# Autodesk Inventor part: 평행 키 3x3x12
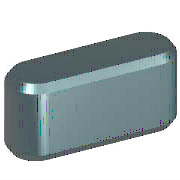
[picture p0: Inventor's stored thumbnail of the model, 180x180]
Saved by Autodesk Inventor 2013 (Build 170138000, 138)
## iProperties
IsCustomPart: 1
Created: 2012-02
Part Number: 평행 키 3x3x12
Material: 강철, 연강
Description: 평행 키
Document SubType Name: Modeling
Standard: JIS B 1301
Designer: mdu-01
Standards Organization: JIS
Language: ko-KR
Size Designation: 3x3x12
Categories: <MemberInstance><Categories><Category DisplayName="샤프트 부품" InternalName="7f7aeb1f-a693-4053-b835-cee3144e0d98" Mnemonic="SHFT"><Category DisplayName="키" Interna
Density: 1 g/cm^3
Author: mdu-01
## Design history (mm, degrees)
workplane "Work Plane1"
workplane "Work Plane2"
sketch "스케치1"
  geometry: L1 (1.5, 1.5)-(10.5, 1.5); L2 (10.5, -1.5)-(1.5, -1.5); L3 (0, 9.4)-(0, -7.4) reference; L4 (-5, 0)-(30, 0) reference; L5 (12, 0)-(12, 7); A1 r 1.5 centre (1.5, 0) between (1.5, 1.5) and (1.5, -1.5); A2 r 1.5 centre (10.5, 0) between (10.5, -1.5) and (10.5, 1.5)
  constraints: 6 end point, 5 point on circle, 4 tangent, 3 point on line, 2 centre point, 1 horizontal, 1 parallel, 1 perpendicular
  dimensions: "d0" = 1.5 radius of A1 (= 0.5 x PB); "d13" = 1.5 radius of A2 (= 0.5 x PB); "d14" = 12 distance between parallel lines of L5 L3 (= NLG)
extrude "본체1" new body sketch "스케치1" taper "d3" = 0 deg; stored distance "d4" = 10
workplane "Work Plane3"
body "Solid1"
chamfer "모따기1" distance "d8" = 0.25 (= PHH); stored, may be unused: second distance "d9" = 0.25 (= PHH), angle "d15" = 45 deg
other parameters: "d1" = -1.8 (= -PNT), "d2" = 1.2 (= PH - PNT), "NLG" = 12 [user parameter; used in 3 equation terms], "PB" = 3 [user parameter; used in 2 equation terms], "PNT" = 1.8 [user parameter; used in 2 equation terms], "PH" = 3 [user parameter; used in 1 equation term], "PHH" = 0.25 [user parameter; used in 2 equation terms], "d10" = 0, "d16" = 0, "d17" = 0, "d18" = 0, "WDMIN" = 8 [user parameter], "PLB2" = 12 (= NLG) [user parameter], "PLB1" = 12 (= NLG) [user parameter], "RR" = 0.08 [user parameter], "PUEB" = 1.4 [user parameter]
